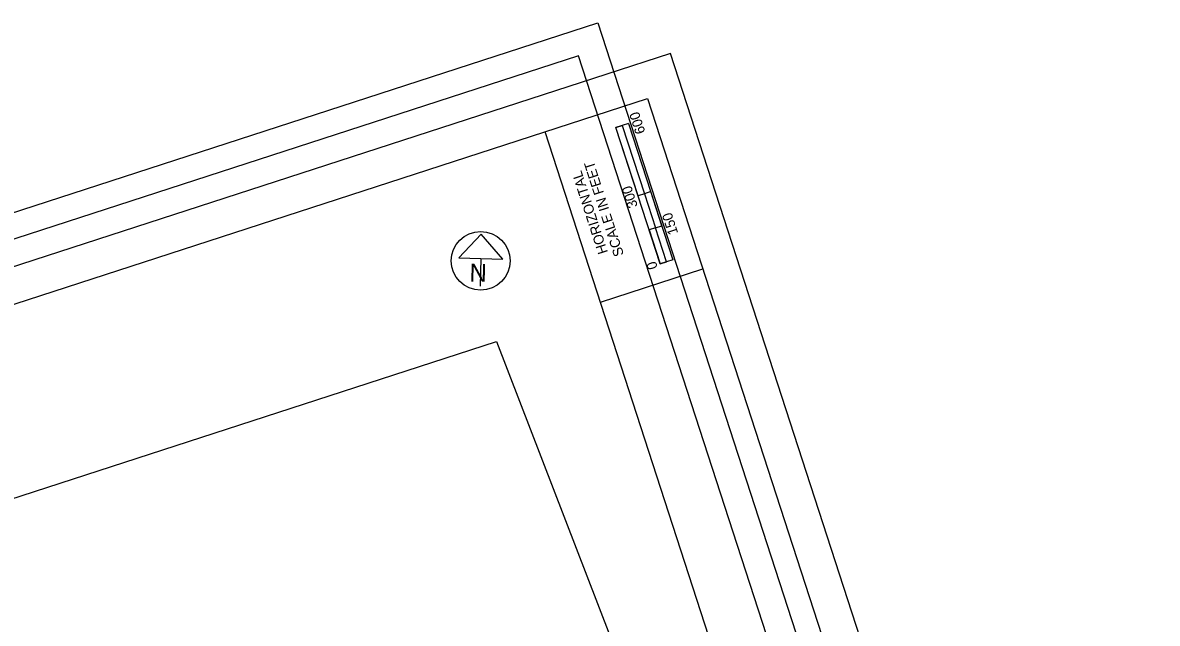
# Model space of a CAD drawing. Extents: x -468563856 to 36492962, y -306094093 to 11899197.
# Drawn here: x 1824382 to 1829131, y 533941 to 536455 of the extents above; entities that cross this region are included whole.
import ezdxf

# ---------------------------------------------------------------- set-up
doc = ezdxf.new("R2010")
doc.units = 0
for name, color, linetype in [('Level 63', 7, 'Continuous'), ('SC_Scratch1', 7, 'Continuous'), ('SH_Border', 7, 'Continuous'), ('SH_Cut_Line', 7, 'Continuous'), ('SH_Data', 7, 'Continuous'), ('SH_Masking', 7, 'Continuous'), ('SH_Text', 7, 'Continuous')]:
    doc.layers.add(name, color=color, linetype=linetype)

msp = doc.modelspace()

# ---------------------------------------------------------------- linework, layer by layer
at = {"layer": 'Level 63'}
for points in [[(1817088.6, 533305.9), (1826789.4, 536455.4), (1828827.2, 530178.6), (1819126.4, 527029.2)], [(1819195.4, 527203), (1828668.6, 530278.5), (1826708.4, 536316.3), (1817235.1, 533240.7)]]:
    msp.add_lwpolyline(points, close=True, dxfattribs=at)
at = {"layer": 'SC_Scratch1'}
msp.add_lwpolyline([(1818754.7, 531265.4), (1818680.3, 532626), (1826365, 535120.9), (1826839.3, 533890.3), (1827446.9, 532018.9), (1827532.1, 531348.3), (1819682.5, 528840.1), (1819362.2, 529394.3)], close=True, dxfattribs=at)
at = {"layer": 'SH_Border'}
for p, q in [((1828514.3, 530006.7), (1826568.9, 535998.8)), ((1826800.5, 535285.4), (1827228.5, 535424.4))]:
    msp.add_line(p, q, dxfattribs=at)
msp.add_lwpolyline([(1817866.1, 533173.3), (1826996.9, 536137.7), (1828942.3, 530145.6), (1819811.4, 527181.2)], close=True, dxfattribs=at)
at = {"layer": 'SH_Cut_Line'}
msp.add_lwpolyline([(1819429.8, 526899.6), (1829131.3, 530049.3), (1827093.3, 536326.7), (1817391.7, 533177)], close=True, dxfattribs=at)
at = {"layer": 'SH_Data'}
for p, q in [((1826918.5, 536033.4), (1826865, 536016.1)), ((1826865, 536016.1), (1826891.7, 536024.7)), ((1827050.3, 535445.4), (1826865, 536016.1)), ((1826957.7, 535730.7), (1826865, 536016.1)), ((1826891.7, 536024.7), (1826891.9, 536024.8)), ((1826891.9, 536024.8), (1826984.5, 535739.4)), ((1826918.5, 536033.4), (1827103.8, 535462.8)), ((1826984.5, 535739.4), (1826957.7, 535730.7)), ((1827010.9, 535748), (1826984.3, 535739.4)), ((1826984.3, 535739.4), (1827030.6, 535596.7)), ((1827057.2, 535605.3), (1827010.9, 535748)), ((1827030.6, 535596.7), (1827004, 535588.1)), ((1827004, 535588.1), (1827050.3, 535445.4)), ((1827030.6, 535596.7), (1827057.2, 535605.3)), ((1827076.9, 535454), (1827030.6, 535596.7)), ((1827103.8, 535462.8), (1827050.3, 535445.4)), ((1827050.3, 535445.4), (1827076.9, 535454))]:
    msp.add_line(p, q, dxfattribs=at)
at = {"layer": 'SH_Masking'}
msp.add_circle((1826299, 535458.4), 123, dxfattribs=at)
at = {"layer": 'SH_Text'}
for p, q in [((1826301.6, 535570.4), (1826207, 535470.3)), ((1826391.5, 535465.9), (1826301.6, 535570.4)), ((1826207, 535470.3), (1826391.5, 535465.9)), ((1826299.2, 535468.1), (1826296.5, 535352.1))]:
    msp.add_line(p, q, dxfattribs=at)
msp.add_circle((1826299, 535458.4), 123, dxfattribs=at)

# ---------------------------------------------------------------- texts
at = {"layer": 'SH_Data'}
for s, p in [('600', (1826989.1, 535997)), ('SCALE IN FEET', (1826899.1, 535484.3)), ('HORIZONTAL', (1826832, 535494.5)), ('300', (1826957.3, 535687.1)), ('150', (1827126.1, 535574.8)), ('0', (1827040.7, 535430.1))]:
    msp.add_text(s, height=42, rotation=107.9864, dxfattribs=at).set_placement(p)
at = {"layer": 'SH_Text'}
msp.add_text('N', height=75, rotation=358.6601, dxfattribs=at).set_placement((1826251.6, 535372))

doc.saveas('drawing.dxf')
